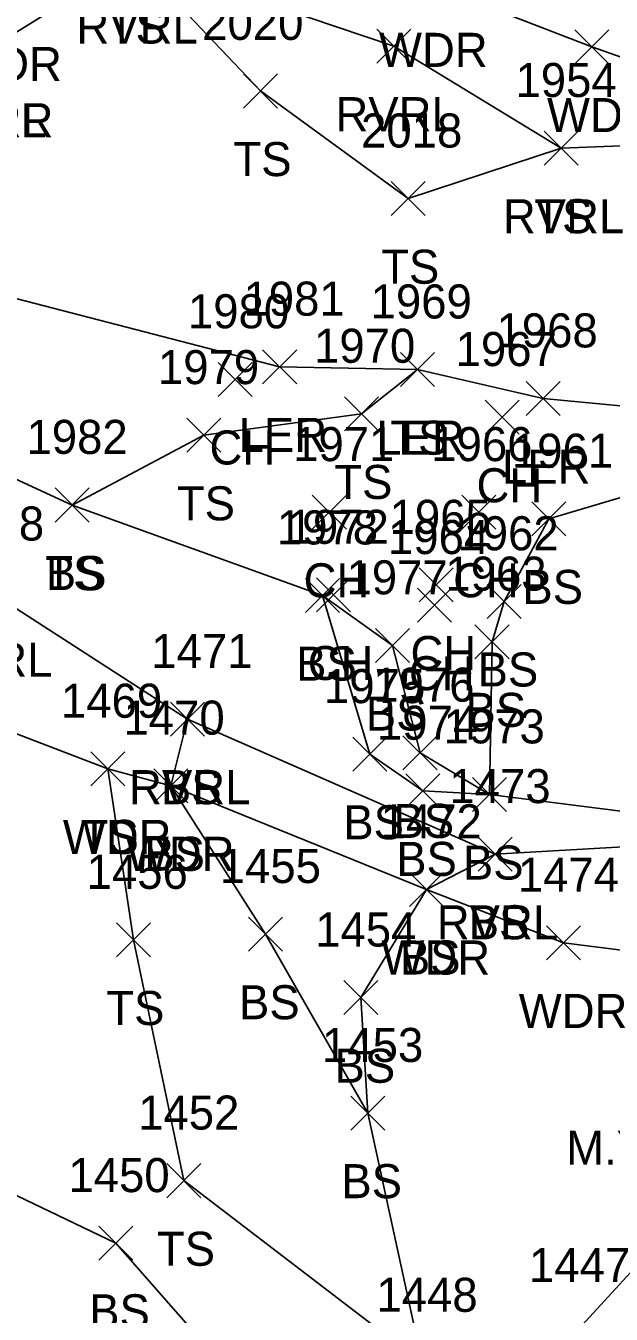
# Model space of a CAD drawing. Extents: x 1600281 to 1602254, y 862855 to 863227.
# Drawn here: x 1601983.1 to 1602017.5, y 863026.2 to 863101.9 of the extents above; entities that cross this region are included whole.
import ezdxf

# ---------------------------------------------------------------- set-up
doc = ezdxf.new("R2010")
doc.units = 0
for name, color, linetype in [('L_A', 7, 'Continuous'), ('L_C', 7, 'Continuous'), ('L_I', 7, 'Continuous'), ('L_TIC', 7, 'Continuous'), ('LARO', 7, 'Continuous'), ('LAWA', 7, 'Continuous'), ('LAWE', 7, 'Continuous'), ('LELB', 7, 'Continuous')]:
    doc.layers.add(name, color=color, linetype=linetype)

msp = doc.modelspace()

# ---------------------------------------------------------------- linework, layer by layer
at = {"layer": 'L_TIC'}
for points in [[(1602003.691, 863099.661), (1602005.691, 863101.661)], [(1602005.691, 863099.661), (1602003.691, 863101.661)], [(1602015.33, 863099.607), (1602017.33, 863101.607)], [(1602017.33, 863099.607), (1602015.33, 863101.607)], [(1601995.85, 863097.022), (1601997.85, 863099.022)], [(1601997.85, 863097.022), (1601995.85, 863099.022)], [(1602013.534, 863093.667), (1602015.534, 863095.667)], [(1602015.534, 863093.667), (1602013.534, 863095.667)], [(1602013.534, 863093.667), (1602015.534, 863095.667)], [(1602015.534, 863093.667), (1602013.534, 863095.667)], [(1602004.535, 863090.701), (1602006.535, 863092.701)], [(1602006.535, 863090.701), (1602004.535, 863092.701)], [(1601996.978, 863080.824), (1601998.978, 863082.824)], [(1601998.978, 863080.824), (1601996.978, 863082.824)], [(1602005.072, 863080.659), (1602007.072, 863082.659)], [(1602007.072, 863080.659), (1602005.072, 863082.659)], [(1602005.072, 863080.659), (1602007.072, 863082.659)], [(1602007.072, 863080.659), (1602005.072, 863082.659)], [(1601994.366, 863080.083), (1601996.366, 863082.083)], [(1601996.366, 863080.083), (1601994.366, 863082.083)], [(1602012.468, 863078.959), (1602014.468, 863080.959)], [(1602014.468, 863078.959), (1602012.468, 863080.959)], [(1602001.78, 863078.057), (1602003.78, 863080.057)], [(1602003.78, 863078.057), (1602001.78, 863080.057)], [(1602010.062, 863077.863), (1602012.062, 863079.863)], [(1602012.062, 863077.863), (1602010.062, 863079.863)], [(1601992.522, 863076.803), (1601994.522, 863078.803)], [(1601994.522, 863076.803), (1601992.522, 863078.803)], [(1601984.789, 863072.704), (1601986.789, 863074.704)], [(1601986.789, 863072.704), (1601984.789, 863074.704)], [(1601984.789, 863072.704), (1601986.789, 863074.704)], [(1601986.789, 863072.704), (1601984.789, 863074.704)], [(1601999.898, 863072.28), (1602001.898, 863074.28)], [(1602001.898, 863072.28), (1601999.898, 863074.28)], [(1602008.686, 863072.281), (1602010.686, 863074.281)], [(1602010.686, 863072.281), (1602008.686, 863074.281)], [(1602012.803, 863071.893), (1602014.803, 863073.893)], [(1602014.803, 863071.893), (1602012.803, 863073.893)], [(1602006.18, 863068.01), (1602008.18, 863070.01)], [(1602008.18, 863068.01), (1602006.18, 863070.01)], [(1601999.504, 863067.388), (1602001.504, 863069.388)], [(1602001.504, 863067.388), (1601999.504, 863069.388)], [(1601999.504, 863067.388), (1602001.504, 863069.388)], [(1602001.504, 863067.388), (1601999.504, 863069.388)], [(1602000.138, 863067.424), (1602002.138, 863069.424)], [(1602002.138, 863067.424), (1602000.138, 863069.424)], [(1602010.17, 863067.044), (1602012.17, 863069.044)], [(1602012.17, 863067.044), (1602010.17, 863069.044)], [(1602006.085, 863066.823), (1602008.085, 863068.823)], [(1602008.085, 863066.823), (1602006.085, 863068.823)], [(1602009.46, 863064.672), (1602011.46, 863066.672)], [(1602011.46, 863064.672), (1602009.46, 863066.672)], [(1602003.602, 863064.455), (1602005.602, 863066.455)], [(1602005.602, 863064.455), (1602003.602, 863066.455)], [(1601991.557, 863060.13), (1601993.557, 863062.13)], [(1601993.557, 863060.13), (1601991.557, 863062.13)], [(1601991.557, 863060.13), (1601993.557, 863062.13)], [(1601993.557, 863060.13), (1601991.557, 863062.13)], [(1602002.277, 863058.068), (1602004.277, 863060.068)], [(1602004.277, 863058.068), (1602002.277, 863060.068)], [(1602005.228, 863058.152), (1602007.228, 863060.152)], [(1602007.228, 863058.152), (1602005.228, 863060.152)], [(1601986.871, 863057.21), (1601988.871, 863059.21)], [(1601988.871, 863057.21), (1601986.871, 863059.21)], [(1601986.871, 863057.21), (1601988.871, 863059.21)], [(1601988.871, 863057.21), (1601986.871, 863059.21)], [(1601990.577, 863056.216), (1601992.577, 863058.216)], [(1601992.577, 863056.216), (1601990.577, 863058.216)], [(1601990.577, 863056.216), (1601992.577, 863058.216)], [(1601992.577, 863056.216), (1601990.577, 863058.216)], [(1602005.388, 863055.918), (1602007.388, 863057.918)], [(1602007.388, 863055.918), (1602005.388, 863057.918)], [(1602009.309, 863055.702), (1602011.309, 863057.702)], [(1602011.309, 863055.702), (1602009.309, 863057.702)], [(1602009.309, 863055.702), (1602011.309, 863057.702)], [(1602011.309, 863055.702), (1602009.309, 863057.702)], [(1602009.649, 863052.195), (1602011.649, 863054.195)], [(1602011.649, 863052.195), (1602009.649, 863054.195)], [(1602009.649, 863052.195), (1602011.649, 863054.195)], [(1602011.649, 863052.195), (1602009.649, 863054.195)], [(1602005.602, 863050.128), (1602007.602, 863052.128)], [(1602007.602, 863050.128), (1602005.602, 863052.128)], [(1602005.602, 863050.128), (1602007.602, 863052.128)], [(1602007.602, 863050.128), (1602005.602, 863052.128)], [(1601996.147, 863047.499), (1601998.147, 863049.499)], [(1601998.147, 863047.499), (1601996.147, 863049.499)], [(1601988.377, 863047.159), (1601990.377, 863049.159)], [(1601990.377, 863047.159), (1601988.377, 863049.159)], [(1602013.671, 863046.985), (1602015.671, 863048.985)], [(1602015.671, 863046.985), (1602013.671, 863048.985)], [(1602001.758, 863043.77), (1602003.758, 863045.77)], [(1602003.758, 863043.77), (1602001.758, 863045.77)], [(1602002.161, 863036.99), (1602004.161, 863038.99)], [(1602004.161, 863036.99), (1602002.161, 863038.99)], [(1602002.161, 863036.99), (1602004.161, 863038.99)], [(1602004.161, 863036.99), (1602002.161, 863038.99)], [(1601991.353, 863033.019), (1601993.353, 863035.019)], [(1601993.353, 863033.019), (1601991.353, 863035.019)], [(1601987.341, 863029.346), (1601989.341, 863031.346)], [(1601989.341, 863029.346), (1601987.341, 863031.346)]]:
    msp.add_lwpolyline(points, dxfattribs=at)
at = {"layer": 'LARO'}
msp.add_lwpolyline([(1602088.591, 863055.936), (1602084.205, 863057.115), (1602072.763, 863055.569), (1602061.695, 863058.699), (1602046.297, 863060.847), (1602041.29, 863063.794), (1602038.414, 863067.763), (1602029.525, 863077.549), (1602024.193, 863078.94), (1602013.468, 863079.959), (1602006.072, 863081.659), (1601997.978, 863081.824), (1601978.825, 863086.781)], dxfattribs=at)
at = {"layer": 'LAWA'}
for points in [[(1602042.214, 863103.013), (1602035.268, 863100.33), (1602027.521, 863096.676), (1602016.33, 863100.607), (1602006.455, 863104.438)], [(1601898.678, 863064.416), (1601911.709, 863050.949), (1601935.902, 863043.881), (1601947.495, 863033.023), (1601951.399, 863041.53), (1601951.325, 863053.197), (1601949.991, 863060.087), (1601958.573, 863066.845), (1601964.294, 863071.516), (1601970.831, 863066.786), (1601979.179, 863061.535), (1601987.871, 863058.21), (1601991.577, 863057.216), (1602006.602, 863051.128), (1602014.671, 863047.985), (1602025.678, 863046.601), (1602024.954, 863036.82), (1602020.118, 863030.26)], [(1601918.484, 862969.325), (1601939.42, 862962.53), (1601955.985, 862947.407), (1601971.758, 862937.876), (1601975.725, 862943.556), (1601990.974, 862965.699), (1602006.102, 862971.122), (1602011.441, 862985.305), (1602010.41, 863001.058), (1602007, 863006.956), (1602005.728, 863016.362), (1602007.852, 863017.624), (1602015.328, 863025.061), (1602020.118, 863030.26)]]:
    msp.add_lwpolyline(points, dxfattribs=at)
at = {"layer": 'LAWE'}
for points in [[(1602053.378, 863085.572), (1602049.014, 863088.599), (1602037.877, 863092.461), (1602027.14, 863095.153), (1602014.534, 863094.667), (1602004.691, 863100.661), (1601989.462, 863105.807), (1601980.589, 863100.305)], [(1601898.678, 863064.416), (1601916.681, 863058.738), (1601936.523, 863051.716), (1601943.718, 863056.806), (1601947.621, 863066.675), (1601950.709, 863072.592), (1601955.751, 863076.087), (1601965.067, 863075.219), (1601980.923, 863068.616), (1601992.557, 863061.13), (1602010.649, 863053.195), (1602028.102, 863054.194), (1602030.833, 863052.803)]]:
    msp.add_lwpolyline(points, dxfattribs=at)
at = {"layer": 'LELB'}
for points in [[(1602014.534, 863094.667), (1602005.535, 863091.701), (1601996.85, 863098.022), (1601989.462, 863105.807)], [(1602006.072, 863081.659), (1602002.78, 863079.057), (1601993.522, 863077.803), (1601985.789, 863073.704)], [(1602030.177, 863055.597), (1602022.043, 863055.22), (1602010.309, 863056.702), (1602006.388, 863056.918), (1602003.277, 863059.068), (1602000.504, 863068.388), (1601985.789, 863073.704), (1601974.066, 863079.098), (1601965.377, 863080.345), (1601950.615, 863075.646)], [(1602029.525, 863077.549), (1602013.803, 863072.893), (1602011.17, 863068.044), (1602010.46, 863065.672), (1602010.309, 863056.702), (1602006.228, 863059.152), (1602004.602, 863065.455), (1602000.504, 863068.388)], [(1602003.161, 863037.99), (1601997.147, 863048.499), (1601991.577, 863057.216), (1601992.557, 863061.13)], [(1602006.36, 863023.315), (1601992.353, 863034.019), (1601989.377, 863048.159), (1601987.871, 863058.21)], [(1601850.487, 862982.969), (1601860.819, 862978.517), (1601879.357, 862968.779), (1601889.404, 862966.06), (1601913.787, 862945.707), (1601936.178, 862934.785), (1601958.999, 862928.536), (1601973.106, 862927.744), (1601983.044, 862929.485), (1601994.912, 862935.464), (1602008.175, 862945.227), (1602016.316, 862961.337), (1602018.761, 862980.317), (1602014.943, 863002.438), (1602007.852, 863017.624), (1602006.36, 863023.315), (1602003.161, 863037.99), (1602002.758, 863044.77), (1602006.602, 863051.128), (1602010.649, 863053.195)], [(1601958.999, 862928.536), (1601972.89, 862929.468), (1601981.162, 862933.435), (1601993.258, 862937.414), (1602005.114, 862948.359), (1602014.99, 862961.982), (1602017.327, 862980.602), (1602012.478, 863001.488), (1602005.728, 863016.362), (1601997.522, 863019.91), (1601988.341, 863030.346), (1601976.19, 863036.164)]]:
    msp.add_lwpolyline(points, dxfattribs=at)

# ---------------------------------------------------------------- texts
at = {"layer": 'L_A'}
for s, p in [('RVRL', (1601986.029, 863100.807)), ('TS', (1601987.871, 863100.807)), ('WDR', (1602003.817, 863099.438)), ('WDR', (1601978.791, 863098.605)), ('RVRL', (1602001.258, 863095.661)), ('WDR', (1602013.693, 863095.607)), ('RVRR', (1601977.101, 863095.305)), ('RVRL', (1601977.156, 863095.305)), ('TS', (1601995.26, 863093.022)), ('RVRL', (1602011.101, 863089.667)), ('TS', (1602012.943, 863089.667)), ('TS', (1602003.944, 863086.701)), ('LER', (1601995.561, 863076.824)), ('TS', (1602004.481, 863076.659)), ('CH', (1601993.854, 863076.083)), ('LER', (1602003.654, 863076.659)), ('LER', (1602011.05, 863074.959)), ('TS', (1602001.189, 863074.057)), ('CH', (1602009.55, 863073.863)), ('TS', (1601991.932, 863072.803)), ('TS', (1601984.199, 863068.704)), ('BS', (1601984.23, 863068.704)), ('CH', (1601999.387, 863068.28)), ('CH', (1602008.175, 863068.281)), ('BS', (1602012.244, 863067.893)), ('CH', (1602005.668, 863064.01)), ('RVRL', (1601977.49, 863063.616)), ('BS', (1601998.945, 863063.388)), ('BS', (1601998.945, 863063.388)), ('CH', (1601999.627, 863063.424)), ('BS', (1602009.611, 863063.044)), ('CH', (1602005.573, 863062.823)), ('BS', (1602003.043, 863060.455)), ('BS', (1602008.901, 863060.672)), ('RVRL', (1601989.124, 863056.13)), ('BS', (1601990.998, 863056.13)), ('BS', (1602001.718, 863054.068)), ('BS', (1602004.669, 863054.152)), ('TS', (1601986.281, 863053.21)), ('WDR', (1601985.233, 863053.21)), ('WDR', (1601988.939, 863052.216)), ('BS', (1601990.018, 863052.216)), ('BS', (1602004.829, 863051.918)), ('BS', (1602008.75, 863051.702)), ('BS', (1602008.75, 863051.702)), ('RVRL', (1602007.216, 863048.195)), ('BS', (1602009.09, 863048.195)), ('WDR', (1602003.964, 863046.128)), ('BS', (1602005.043, 863046.128)), ('BS', (1601995.588, 863043.499)), ('TS', (1601987.786, 863043.159)), ('WDR', (1602012.033, 863042.985)), ('BS', (1602001.199, 863039.77)), ('BS', (1602001.602, 863032.99)), ('BS', (1602001.602, 863032.99)), ('TS', (1601990.762, 863029.019)), ('BS', (1601986.782, 863025.346))]:
    msp.add_text(s, height=2, dxfattribs=at).set_placement(p)
at = {"layer": 'L_C'}
msp.add_text('M.YELLOW BIRCH', height=2, dxfattribs=at).set_placement((1602014.817, 863034.949))
at = {"layer": 'L_I'}
for s, p in [('2020', (1601993.425, 863101.022)), ('1954', (1602011.841, 863097.667)), ('1954', (1602011.841, 863097.667)), ('2018', (1602002.763, 863094.701)), ('1981', (1601995.852, 863084.824)), ('1969', (1602003.324, 863084.659)), ('1969', (1602003.324, 863084.659)), ('1980', (1601992.586, 863084.083)), ('1968', (1602010.727, 863082.959)), ('1970', (1602000, 863082.057)), ('1967', (1602008.322, 863081.863)), ('1979', (1601990.822, 863080.803)), ('1982', (1601983.096, 863076.704)), ('1982', (1601983.096, 863076.704)), ('1971', (1601998.772, 863076.28)), ('1966', (1602006.891, 863076.281)), ('1961', (1602011.629, 863075.893)), ('1468', (1601978.183, 863071.616)), ('1978', (1601997.811, 863071.388)), ('1978', (1601997.811, 863071.388)), ('1972', (1601998.445, 863071.424)), ('1965', (1602004.44, 863072.01)), ('1964', (1602004.345, 863070.823)), ('1962', (1602008.43, 863071.044)), ('1977', (1602001.909, 863068.455)), ('1963', (1602007.72, 863068.672)), ('1471', (1601990.431, 863064.13)), ('1471', (1601990.431, 863064.13)), ('1975', (1602000.584, 863062.068)), ('1976', (1602003.48, 863062.152)), ('1469', (1601985.123, 863061.21)), ('1469', (1601985.123, 863061.21)), ('1470', (1601988.797, 863060.216)), ('1470', (1601988.797, 863060.216)), ('1974', (1602003.695, 863059.918)), ('1973', (1602007.616, 863059.702)), ('1973', (1602007.616, 863059.702)), ('1473', (1602007.956, 863056.195)), ('1473', (1602007.956, 863056.195)), ('1472', (1602003.909, 863054.128)), ('1472', (1602003.909, 863054.128)), ('1456', (1601986.629, 863051.159)), ('1455', (1601994.454, 863051.499)), ('1474', (1602011.978, 863050.985)), ('1454', (1602000.065, 863047.77)), ('1453', (1602000.468, 863040.99)), ('1453', (1602000.468, 863040.99)), ('1452', (1601989.66, 863037.019)), ('1450', (1601985.561, 863033.346)), ('1447', (1602012.635, 863028.061)), ('1448', (1602003.667, 863026.315)), ('1448', (1602003.667, 863026.315))]:
    msp.add_text(s, height=2, dxfattribs=at).set_placement(p)

doc.saveas('drawing.dxf')
